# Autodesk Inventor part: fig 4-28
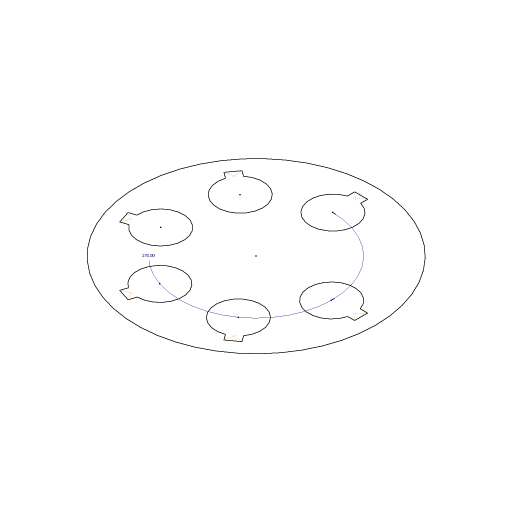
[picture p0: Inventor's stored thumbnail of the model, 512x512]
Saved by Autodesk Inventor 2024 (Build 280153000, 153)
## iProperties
Created: 2004-05
Part Number: fig 4-28
Document SubType Name: Modeling
Designer: CADCIM Technologies
Manufacturer: Standard
Standards Organization: Custom
Density: 1 g/cm^3
Material: Generic
Appearance: Default
Author: CADCIM Technologies
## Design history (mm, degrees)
sketch "Sketch2"
  geometry: L1 (0.73, 11.049)-(0.73, 11.828); L2 (0.73, 11.828)-(-0.73, 11.828); L3 (-0.73, 11.828)-(-0.73, 11.006); L4 (-0.152, 11.061)-(0.73, 11.828); L5 (0.152, 11.061)-(-0.73, 11.828); L6 (-8.51, 7.085)-(-9.14, 7.543); L7 (-9.14, 7.543)-(-9.998, 6.362); L8 (-9.998, 6.362)-(-9.333, 5.879); L9 (-9.038, 6.378)-(-9.14, 7.543); L10 (-8.859, 6.625)-(-9.998, 6.362); L11 (-10.734, -2.72)-(-11.474, -2.961); L12 (-11.474, -2.961)-(-11.023, -4.349); L13 (-11.023, -4.349)-(-10.242, -4.095); L14 (-10.472, -3.563)-(-11.474, -2.961); L15 (-10.566, -3.273)-(-11.023, -4.349); L16 (-4.108, -10.283)-(-4.349, -11.023); L17 (-4.349, -11.023)-(-2.961, -11.474); L18 (-2.961, -11.474)-(-2.707, -10.693); L19 (-3.273, -10.566)-(-4.349, -11.023); L20 (-3.563, -10.472)-(-2.961, -11.474); L21 (5.904, -9.368)-(6.362, -9.998); L22 (6.362, -9.998)-(7.543, -9.14); L23 (7.543, -9.14)-(7.06, -8.475); L24 (6.625, -8.859)-(6.362, -9.998); L25 (6.378, -9.038)-(7.543, -9.14); L26 (11.049, -0.73)-(11.828, -0.73); L27 (11.828, -0.73)-(11.828, 0.73); L28 (11.828, 0.73)-(11.006, 0.73); L29 (11.061, 0.152)-(11.828, -0.73); L30 (11.061, -0.152)-(11.828, 0.73); C1 r 13.473 at (0, 0); A1 r 2.558 centre (0.072, 8.577) between (-0.73, 11.006) and (0.73, 11.049); A2 r 2.558 centre (-6.897, 5.1) between (-9.333, 5.879) and (-8.51, 7.085); A3 r 2.558 centre (-8.18, -2.582) between (-10.242, -4.095) and (-10.734, -2.72); A4 r 2.558 centre (-2.719, -8.135) between (-2.707, -10.693) and (-4.108, -10.283); A5 r 2.558 centre (4.983, -6.981) between (7.06, -8.475) and (5.904, -9.368); A6 r 2.558 centre (8.577, -0.072) between (11.006, 0.73) and (11.049, -0.73); 6 further points
  constraints: 60 end point, 12 point on circle, 7 centre point, 2 coincident, 1 parallel, 70 other
  dimensions: "d6" = 270 deg dimension on point (0, 0) A1.centre A6.centre
